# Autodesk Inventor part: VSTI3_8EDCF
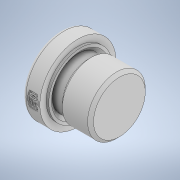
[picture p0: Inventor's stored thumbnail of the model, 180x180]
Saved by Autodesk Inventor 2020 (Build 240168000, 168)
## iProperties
Created: 2019-12
Part Number: VSTI3_8EDCF
Material: Generico
Description: STEP AP203
Document SubType Name: Modeling
Designer: carlo
Density: 1 g/cm^3
Appearance: Default
Sending System: PARTsolutions
DataBaseUnit: MM
Title: p:/temp/worker_148/temp/exporttempdir_1280_916_47ucM/format_0/EO Verschluss-Stopfen fuer Einschraubloecher VSTI3_8EDCF.stp
Revision Number: NONE
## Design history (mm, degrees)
feature "_EO Verschluss-Stopfen fuer Einschraubloecher VSTI3_8EDCF"
node "Piano di lavoro1"
node "Piano di lavoro2"
node "Asse di lavoro1"
node "Solido1"
other parameters: "d0" = 0, "d1" = 0
